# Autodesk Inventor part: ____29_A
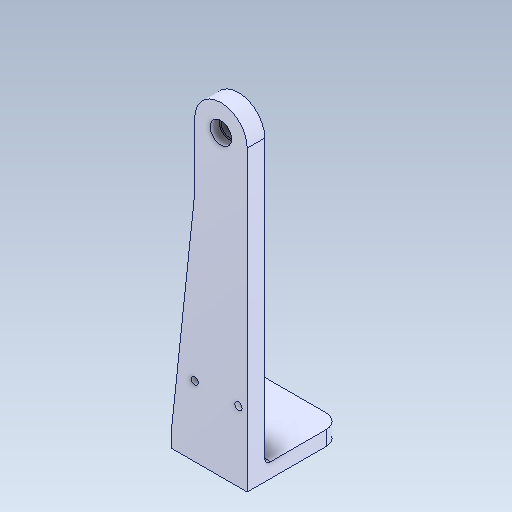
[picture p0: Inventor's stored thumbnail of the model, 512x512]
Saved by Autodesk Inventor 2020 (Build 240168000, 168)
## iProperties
Created: 2017-09
Part Number: ____29_A
Material: Générique
Document SubType Name: Modeling
Designer: bruno
Density: 1 g/cm^3
Appearance: Par défaut
Author: bruno
Sending System: SolidWorks 2016
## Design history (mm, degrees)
feature "Importée1"
node "Solide1"
